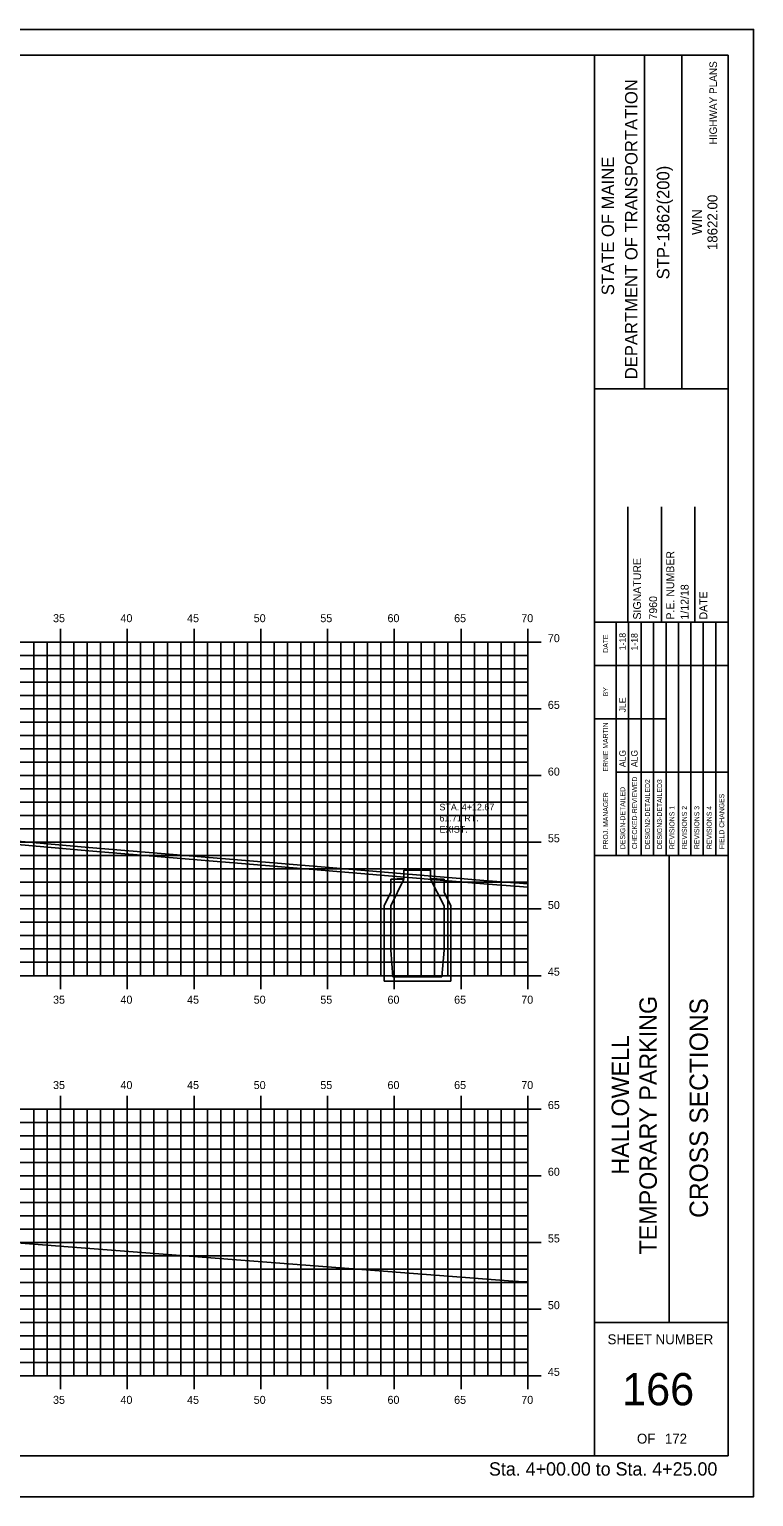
# Model space of a CAD drawing. Extents: x 1026213 to 1026383, y 394615 to 394725.
# Drawn here: x 1026329.1 to 1026383.3, y 394614.9 to 394724.9 of the extents above; entities that cross this region are included whole.
import ezdxf

# ---------------------------------------------------------------- set-up
doc = ezdxf.new("R2010")
doc.units = 0
for name, color, linetype in [('BORDER', 7, 'Continuous'), ('D_Text_Monospaced', 7, 'Continuous'), ('H_V ANNOTATION', 7, 'Continuous'), ('HIGHWAY_TITLE', 7, 'Continuous'), ('MAJOR', 7, 'Continuous'), ('MINOR', 7, 'Continuous'), ('PLOT BOUNDARY', 7, 'Continuous'), ('S_Roadway_Centerline', 7, 'Continuous'), ('S_Utilities_UG_Sanitary_MH', 7, 'Continuous')]:
    doc.layers.add(name, color=color, linetype=linetype)

msp = doc.modelspace()

# ---------------------------------------------------------------- linework, layer by layer
at = {"layer": 'BORDER'}
for p, q in [((1026381.43, 394722.93), (1026221.43, 394722.93)), ((1026371.43, 394617.93), (1026371.43, 394722.94)), ((1026375.16, 394697.93), (1026375.16, 394722.93)), ((1026377.96, 394697.93), (1026377.96, 394722.93)), ((1026381.43, 394617.93), (1026381.43, 394722.93)), ((1026371.43, 394697.93), (1026381.43, 394697.93)), ((1026373.93, 394680.44), (1026373.93, 394689.08)), ((1026376.43, 394680.44), (1026376.43, 394689.08)), ((1026378.93, 394680.44), (1026378.93, 394689.08)), ((1026371.43, 394680.44), (1026381.43, 394680.44)), ((1026371.43, 394662.94), (1026381.43, 394662.94)), ((1026377.02, 394627.94), (1026377.02, 394662.94)), ((1026371.43, 394627.94), (1026381.43, 394627.94)), ((1026221.43, 394617.93), (1026381.43, 394617.93))]:
    msp.add_line(p, q, dxfattribs=at)
for points in [[(1026373.05, 394677.19), (1026373.05, 394680.44)], [(1026373.98, 394662.94), (1026373.98, 394680.44)], [(1026374.91, 394680.44), (1026374.91, 394662.94)], [(1026375.84, 394662.94), (1026375.84, 394680.44)], [(1026376.78, 394662.94), (1026376.78, 394680.44)], [(1026377.71, 394662.94), (1026377.71, 394680.44)], [(1026378.64, 394662.94), (1026378.64, 394680.44)], [(1026379.57, 394662.94), (1026379.57, 394680.44)], [(1026380.5, 394662.94), (1026380.5, 394680.44)], [(1026373.05, 394662.94), (1026373.05, 394679.73)], [(1026371.43, 394677.19), (1026381.43, 394677.19)], [(1026371.43, 394673.19), (1026373.05, 394673.19)], [(1026373.05, 394673.19), (1026376.78, 394673.19)], [(1026373.05, 394669.19), (1026381.43, 394669.19)]]:
    msp.add_lwpolyline(points, dxfattribs=at)
at = {"layer": 'MAJOR'}
for p, q in [((1026226.43, 394678.93), (1026366.43, 394678.93)), ((1026331.43, 394679.93), (1026331.43, 394678.93)), ((1026331.43, 394653.93), (1026331.43, 394678.93)), ((1026336.43, 394679.93), (1026336.43, 394678.93)), ((1026336.43, 394653.93), (1026336.43, 394678.93)), ((1026341.43, 394679.93), (1026341.43, 394678.93)), ((1026341.43, 394653.93), (1026341.43, 394678.93)), ((1026346.43, 394679.93), (1026346.43, 394678.93)), ((1026346.43, 394653.93), (1026346.43, 394678.93)), ((1026351.43, 394679.93), (1026351.43, 394678.93)), ((1026351.43, 394653.93), (1026351.43, 394678.93)), ((1026356.43, 394679.93), (1026356.43, 394678.93)), ((1026356.43, 394653.93), (1026356.43, 394678.93)), ((1026361.43, 394679.93), (1026361.43, 394678.93)), ((1026361.43, 394653.93), (1026361.43, 394678.93)), ((1026367.44, 394678.93), (1026365.43, 394678.93)), ((1026366.43, 394679.93), (1026366.43, 394678.93)), ((1026366.43, 394653.93), (1026366.43, 394678.93)), ((1026226.43, 394673.93), (1026366.43, 394673.93)), ((1026367.44, 394673.93), (1026365.43, 394673.93)), ((1026226.43, 394668.93), (1026366.43, 394668.93)), ((1026367.44, 394668.93), (1026365.43, 394668.93)), ((1026226.43, 394663.93), (1026366.43, 394663.93)), ((1026367.44, 394663.93), (1026365.43, 394663.93)), ((1026226.43, 394658.93), (1026366.43, 394658.93)), ((1026367.44, 394658.93), (1026365.43, 394658.93)), ((1026226.43, 394653.93), (1026366.43, 394653.93)), ((1026331.43, 394652.93), (1026331.43, 394653.93)), ((1026336.43, 394652.93), (1026336.43, 394653.93)), ((1026341.43, 394652.93), (1026341.43, 394653.93)), ((1026346.43, 394652.93), (1026346.43, 394653.93)), ((1026351.43, 394652.93), (1026351.43, 394653.93)), ((1026356.43, 394652.93), (1026356.43, 394653.93)), ((1026361.43, 394652.93), (1026361.43, 394653.93)), ((1026367.44, 394653.93), (1026365.43, 394653.93)), ((1026366.43, 394652.93), (1026366.43, 394653.93)), ((1026331.43, 394644.93), (1026331.43, 394643.93)), ((1026336.43, 394644.93), (1026336.43, 394643.93)), ((1026341.43, 394644.93), (1026341.43, 394643.93)), ((1026346.43, 394644.93), (1026346.43, 394643.93)), ((1026351.43, 394644.93), (1026351.43, 394643.93)), ((1026356.43, 394644.93), (1026356.43, 394643.93)), ((1026361.43, 394644.93), (1026361.43, 394643.93)), ((1026366.43, 394644.93), (1026366.43, 394643.93)), ((1026226.43, 394643.93), (1026366.43, 394643.93)), ((1026331.43, 394623.93), (1026331.43, 394643.93)), ((1026336.43, 394623.93), (1026336.43, 394643.93)), ((1026341.43, 394623.93), (1026341.43, 394643.93)), ((1026346.43, 394623.93), (1026346.43, 394643.93)), ((1026351.43, 394623.93), (1026351.43, 394643.93)), ((1026356.43, 394623.93), (1026356.43, 394643.93)), ((1026361.43, 394623.93), (1026361.43, 394643.93)), ((1026367.44, 394643.93), (1026365.43, 394643.93)), ((1026366.43, 394623.93), (1026366.43, 394643.93)), ((1026226.43, 394638.93), (1026366.43, 394638.93)), ((1026367.44, 394638.93), (1026365.43, 394638.93)), ((1026226.43, 394633.93), (1026366.43, 394633.93)), ((1026367.44, 394633.93), (1026365.43, 394633.93)), ((1026226.43, 394628.93), (1026366.43, 394628.93)), ((1026367.44, 394628.93), (1026365.43, 394628.93)), ((1026226.43, 394623.93), (1026366.43, 394623.93)), ((1026331.43, 394622.93), (1026331.43, 394623.93)), ((1026336.43, 394622.93), (1026336.43, 394623.93)), ((1026341.43, 394622.93), (1026341.43, 394623.93)), ((1026346.43, 394622.93), (1026346.43, 394623.93)), ((1026351.43, 394622.93), (1026351.43, 394623.93)), ((1026356.43, 394622.93), (1026356.43, 394623.93)), ((1026361.43, 394622.93), (1026361.43, 394623.93)), ((1026367.44, 394623.93), (1026365.43, 394623.93)), ((1026366.43, 394622.93), (1026366.43, 394623.93))]:
    msp.add_line(p, q, dxfattribs=at)
at = {"layer": 'MINOR'}
for p, q in [((1026329.43, 394653.93), (1026329.43, 394678.93)), ((1026330.43, 394653.93), (1026330.43, 394678.93)), ((1026332.43, 394653.93), (1026332.43, 394678.93)), ((1026333.43, 394653.93), (1026333.43, 394678.93)), ((1026334.43, 394653.93), (1026334.43, 394678.93)), ((1026335.43, 394653.93), (1026335.43, 394678.93)), ((1026337.43, 394653.93), (1026337.43, 394678.93)), ((1026338.43, 394653.93), (1026338.43, 394678.93)), ((1026339.43, 394653.93), (1026339.43, 394678.93)), ((1026340.43, 394653.93), (1026340.43, 394678.93)), ((1026342.43, 394653.93), (1026342.43, 394678.93)), ((1026343.43, 394653.93), (1026343.43, 394678.93)), ((1026344.43, 394653.93), (1026344.43, 394678.93)), ((1026345.43, 394653.93), (1026345.43, 394678.93)), ((1026347.43, 394653.93), (1026347.43, 394678.93)), ((1026348.43, 394653.93), (1026348.43, 394678.93)), ((1026349.43, 394653.93), (1026349.43, 394678.93)), ((1026350.43, 394653.93), (1026350.43, 394678.93)), ((1026352.43, 394653.93), (1026352.43, 394678.93)), ((1026353.43, 394653.93), (1026353.43, 394678.93)), ((1026354.43, 394653.93), (1026354.43, 394678.93)), ((1026355.43, 394653.93), (1026355.43, 394678.93)), ((1026357.43, 394653.93), (1026357.43, 394678.93)), ((1026358.43, 394653.93), (1026358.43, 394678.93)), ((1026359.43, 394653.93), (1026359.43, 394678.93)), ((1026360.43, 394653.93), (1026360.43, 394678.93)), ((1026362.43, 394653.93), (1026362.43, 394678.93)), ((1026363.43, 394653.93), (1026363.43, 394678.93)), ((1026364.43, 394653.93), (1026364.43, 394678.93)), ((1026365.43, 394653.93), (1026365.43, 394678.93)), ((1026226.43, 394677.93), (1026366.43, 394677.93)), ((1026366.43, 394677.93), (1026365.43, 394677.93)), ((1026226.43, 394676.93), (1026366.43, 394676.93)), ((1026366.43, 394676.93), (1026365.43, 394676.93)), ((1026226.43, 394675.93), (1026366.43, 394675.93)), ((1026366.43, 394675.93), (1026365.43, 394675.93)), ((1026226.43, 394674.93), (1026366.43, 394674.93)), ((1026366.43, 394674.93), (1026365.43, 394674.93)), ((1026226.43, 394672.93), (1026366.43, 394672.93)), ((1026366.43, 394672.93), (1026365.43, 394672.93)), ((1026226.43, 394671.93), (1026366.43, 394671.93)), ((1026366.43, 394671.93), (1026365.43, 394671.93)), ((1026226.43, 394670.93), (1026366.43, 394670.93)), ((1026366.43, 394670.93), (1026365.43, 394670.93)), ((1026226.43, 394669.93), (1026366.43, 394669.93)), ((1026366.43, 394669.93), (1026365.43, 394669.93)), ((1026226.43, 394667.93), (1026366.43, 394667.93)), ((1026366.43, 394667.93), (1026365.43, 394667.93)), ((1026226.43, 394666.93), (1026366.43, 394666.93)), ((1026366.43, 394666.93), (1026365.43, 394666.93)), ((1026226.43, 394665.93), (1026366.43, 394665.93)), ((1026366.43, 394665.93), (1026365.43, 394665.93)), ((1026226.43, 394664.93), (1026366.43, 394664.93)), ((1026366.43, 394664.93), (1026365.43, 394664.93)), ((1026226.43, 394662.93), (1026366.43, 394662.93)), ((1026366.43, 394662.93), (1026365.43, 394662.93)), ((1026226.43, 394661.93), (1026366.43, 394661.93)), ((1026366.43, 394661.93), (1026365.43, 394661.93)), ((1026226.43, 394660.93), (1026366.43, 394660.93)), ((1026366.43, 394660.93), (1026365.43, 394660.93)), ((1026226.43, 394659.93), (1026366.43, 394659.93)), ((1026366.43, 394659.93), (1026365.43, 394659.93)), ((1026226.43, 394657.93), (1026366.43, 394657.93)), ((1026226.43, 394656.93), (1026366.43, 394656.93)), ((1026366.43, 394657.93), (1026365.43, 394657.93)), ((1026366.43, 394656.93), (1026365.43, 394656.93)), ((1026226.43, 394655.93), (1026366.43, 394655.93)), ((1026366.43, 394655.93), (1026365.43, 394655.93)), ((1026226.43, 394654.93), (1026366.43, 394654.93)), ((1026366.43, 394654.93), (1026365.43, 394654.93)), ((1026329.43, 394623.93), (1026329.43, 394643.93)), ((1026330.43, 394623.93), (1026330.43, 394643.93)), ((1026332.43, 394623.93), (1026332.43, 394643.93)), ((1026333.43, 394623.93), (1026333.43, 394643.93)), ((1026334.43, 394623.93), (1026334.43, 394643.93)), ((1026335.43, 394623.93), (1026335.43, 394643.93)), ((1026337.43, 394623.93), (1026337.43, 394643.93)), ((1026338.43, 394623.93), (1026338.43, 394643.93)), ((1026339.43, 394623.93), (1026339.43, 394643.93)), ((1026340.43, 394623.93), (1026340.43, 394643.93)), ((1026342.43, 394623.93), (1026342.43, 394643.93)), ((1026343.43, 394623.93), (1026343.43, 394643.93)), ((1026344.43, 394623.93), (1026344.43, 394643.93)), ((1026345.43, 394623.93), (1026345.43, 394643.93)), ((1026347.43, 394623.93), (1026347.43, 394643.93)), ((1026348.43, 394623.93), (1026348.43, 394643.93)), ((1026349.43, 394623.93), (1026349.43, 394643.93)), ((1026350.43, 394623.93), (1026350.43, 394643.93)), ((1026352.43, 394623.93), (1026352.43, 394643.93)), ((1026353.43, 394623.93), (1026353.43, 394643.93)), ((1026354.43, 394623.93), (1026354.43, 394643.93)), ((1026355.43, 394623.93), (1026355.43, 394643.93)), ((1026357.43, 394623.93), (1026357.43, 394643.93)), ((1026358.43, 394623.93), (1026358.43, 394643.93)), ((1026359.43, 394623.93), (1026359.43, 394643.93)), ((1026360.43, 394623.93), (1026360.43, 394643.93)), ((1026362.43, 394623.93), (1026362.43, 394643.93)), ((1026363.43, 394623.93), (1026363.43, 394643.93)), ((1026364.43, 394623.93), (1026364.43, 394643.93)), ((1026365.43, 394623.93), (1026365.43, 394643.93)), ((1026226.43, 394642.93), (1026366.43, 394642.93)), ((1026366.43, 394642.93), (1026365.43, 394642.93)), ((1026226.43, 394641.93), (1026366.43, 394641.93)), ((1026366.43, 394641.93), (1026365.43, 394641.93)), ((1026226.43, 394640.93), (1026366.43, 394640.93)), ((1026366.43, 394640.93), (1026365.43, 394640.93)), ((1026226.43, 394639.93), (1026366.43, 394639.93)), ((1026366.43, 394639.93), (1026365.43, 394639.93)), ((1026226.43, 394637.93), (1026366.43, 394637.93)), ((1026366.43, 394637.93), (1026365.43, 394637.93)), ((1026226.43, 394636.93), (1026366.43, 394636.93)), ((1026366.43, 394636.93), (1026365.43, 394636.93)), ((1026226.43, 394635.93), (1026366.43, 394635.93)), ((1026226.43, 394634.93), (1026366.43, 394634.93)), ((1026366.43, 394635.93), (1026365.43, 394635.93)), ((1026366.43, 394634.93), (1026365.43, 394634.93)), ((1026226.43, 394632.93), (1026366.43, 394632.93)), ((1026366.43, 394632.93), (1026365.43, 394632.93)), ((1026226.43, 394631.93), (1026366.43, 394631.93)), ((1026366.43, 394631.93), (1026365.43, 394631.93)), ((1026226.43, 394630.93), (1026366.43, 394630.93)), ((1026366.43, 394630.93), (1026365.43, 394630.93)), ((1026226.43, 394629.93), (1026366.43, 394629.93)), ((1026366.43, 394629.93), (1026365.43, 394629.93)), ((1026226.43, 394627.93), (1026366.43, 394627.93)), ((1026366.43, 394627.93), (1026365.43, 394627.93)), ((1026226.43, 394626.93), (1026366.43, 394626.93)), ((1026366.43, 394626.93), (1026365.43, 394626.93)), ((1026226.43, 394625.93), (1026366.43, 394625.93)), ((1026366.43, 394625.93), (1026365.43, 394625.93)), ((1026226.43, 394624.93), (1026366.43, 394624.93)), ((1026366.43, 394624.93), (1026365.43, 394624.93))]:
    msp.add_line(p, q, dxfattribs=at)
at = {"layer": 'PLOT BOUNDARY'}
msp.add_lwpolyline([(1026213.34, 394614.87), (1026383.34, 394614.87), (1026383.34, 394724.87), (1026213.34, 394724.87)], close=True, dxfattribs=at)
at = {"layer": 'S_Roadway_Centerline'}
for points in [[(1026256.36, 394669.08), (1026256.36, 394669.08), (1026258.36, 394668.94), (1026278.77, 394667.41), (1026280.04, 394667.3), (1026280.16, 394667.29), (1026299.85, 394666.05), (1026302.39, 394665.94), (1026303.98, 394665.86), (1026303.98, 394665.86), (1026303.98, 394665.86), (1026309.14, 394665.64), (1026309.14, 394665.64), (1026312.05, 394665.32), (1026323.69, 394664.41), (1026333.54, 394663.54), (1026333.54, 394663.54), (1026333.55, 394663.54), (1026346.49, 394662.46), (1026346.49, 394662.46), (1026363.44, 394661.04), (1026365.47, 394660.9), (1026365.47, 394660.9), (1026366.43, 394660.82)], [(1026256.36, 394668.83), (1026256.36, 394668.83), (1026258.36, 394668.69), (1026278.77, 394667.16), (1026280.04, 394667.05), (1026280.16, 394667.04), (1026299.85, 394665.8), (1026302.39, 394665.69), (1026303.98, 394665.61), (1026303.98, 394665.61), (1026303.98, 394665.61), (1026309.14, 394665.39), (1026309.14, 394665.39), (1026312.05, 394665.07), (1026323.69, 394664.16), (1026333.54, 394663.29), (1026333.54, 394663.29), (1026333.55, 394663.29), (1026346.49, 394662.21), (1026346.49, 394662.21), (1026363.44, 394660.79), (1026365.47, 394660.65), (1026365.47, 394660.65), (1026366.43, 394660.57)], [(1026328.45, 394633.87), (1026365.64, 394631.01), (1026365.64, 394631.01), (1026365.73, 394631.01), (1026366.43, 394630.97)]]:
    msp.add_lwpolyline(points, dxfattribs=at)
at = {"layer": 'S_Utilities_UG_Sanitary_MH'}
for p, q in [((1026356.16, 394661.16), (1026357.15, 394661.16)), ((1026357.15, 394661.16), (1026356.16, 394659.16)), ((1026356.16, 394660.18), (1026356.16, 394661.16)), ((1026356.16, 394661.16), (1026357.15, 394661.16)), ((1026357.15, 394661.16), (1026356.16, 394659.16)), ((1026356.16, 394660.18), (1026356.16, 394661.16)), ((1026360.16, 394659.16), (1026359.15, 394661.16)), ((1026359.15, 394661.16), (1026360.16, 394661.16)), ((1026360.16, 394659.16), (1026359.15, 394661.16)), ((1026359.15, 394661.16), (1026360.16, 394661.16)), ((1026360.16, 394661.16), (1026360.16, 394660.18)), ((1026360.16, 394661.16), (1026360.16, 394660.18)), ((1026355.67, 394659.16), (1026356.16, 394660.18)), ((1026355.67, 394659.16), (1026356.16, 394660.18)), ((1026355.67, 394653.52), (1026355.67, 394659.16)), ((1026355.67, 394653.52), (1026355.67, 394659.16)), ((1026356.16, 394659.16), (1026356.16, 394655.85)), ((1026356.16, 394659.16), (1026356.16, 394655.85)), ((1026360.16, 394660.18), (1026360.66, 394659.16)), ((1026360.16, 394660.18), (1026360.66, 394659.16)), ((1026360.16, 394655.85), (1026360.16, 394659.16)), ((1026360.16, 394655.85), (1026360.16, 394659.16)), ((1026360.66, 394659.16), (1026360.66, 394653.52)), ((1026360.66, 394659.16), (1026360.66, 394653.52)), ((1026356.16, 394655.85), (1026356.33, 394653.84)), ((1026356.16, 394655.85), (1026356.33, 394653.84)), ((1026360, 394653.84), (1026360.16, 394655.85)), ((1026360, 394653.84), (1026360.16, 394655.85)), ((1026356.33, 394653.84), (1026360, 394653.84)), ((1026356.33, 394653.84), (1026360, 394653.84)), ((1026360.66, 394653.52), (1026355.67, 394653.52)), ((1026360.66, 394653.52), (1026355.67, 394653.52))]:
    msp.add_line(p, q, dxfattribs=at)
msp.add_lwpolyline([(1026359.64, 394661.2), (1026359.15, 394661.2), (1026359.15, 394661.83), (1026357.15, 394661.83), (1026357.15, 394661.2), (1026356.65, 394661.2)], dxfattribs=at)
msp.add_lwpolyline([(1026359.64, 394661.2), (1026359.15, 394661.2), (1026359.15, 394661.83), (1026357.15, 394661.83), (1026357.15, 394661.2), (1026356.65, 394661.2)], dxfattribs=at)

# ---------------------------------------------------------------- texts
at = {"layer": 'BORDER'}
for s, height, rotation, p in [('DEPARTMENT OF TRANSPORTATION', 0.9318, 90, (1026374.64, 394698.64)), ('STATE OF MAINE', 0.9318, 90, (1026372.89, 394704.94)), ('STP-1862(200)', 0.9318, 90, (1026377.03, 394706.13)), ('18622.00', 0.745, 90, (1026380.63, 394708.32)), ('WIN', 0.745, 90, (1026379.47, 394709.46)), ('P.E. NUMBER', 0.5906, 90, (1026377.39, 394680.63)), ('SIGNATURE', 0.591, 90, (1026374.91, 394680.63)), ('7960', 0.591, 90, (1026376.11, 394680.63)), ('1/12/18', 0.591, 90, (1026378.47, 394680.63)), ('DATE', 0.591, 90, (1026379.87, 394680.63)), ('DATE', 0.371, 90, (1026372.44, 394678.14)), ('1-18', 0.485, 90, (1026373.76, 394678.33)), ('1-18', 0.485, 90, (1026374.65, 394678.31)), ('BY', 0.371, 90, (1026372.44, 394674.87)), ('JLE', 0.485, 90, (1026373.76, 394673.67)), ('ERNIE MARTIN', 0.3727, 90, (1026372.44, 394669.23)), ('ALG', 0.485, 90, (1026373.76, 394669.56)), ('ALG', 0.485, 90, (1026374.65, 394669.56)), ('DESIGN-DETAILED', 0.3727, 90, (1026373.72, 394663.42)), ('CHECKED-REVIEWED', 0.3727, 90, (1026374.61, 394663.42)), ('DESIGN2-DETAILED2', 0.3727, 90, (1026375.58, 394663.42)), ('DESIGN3-DETAILED3', 0.3727, 90, (1026376.48, 394663.42)), ('PROJ. MANAGER', 0.3727, 90, (1026372.44, 394663.42)), ('FIELD CHANGES', 0.3727, 90, (1026381.14, 394663.42)), ('REVISIONS 1', 0.3727, 90, (1026377.41, 394663.42)), ('REVISIONS 2', 0.3727, 90, (1026378.34, 394663.42)), ('REVISIONS 3', 0.3727, 90, (1026379.27, 394663.42)), ('REVISIONS 4', 0.3727, 90, (1026380.2, 394663.42)), ('CROSS SECTIONS', 1.3779, 90, (1026379.92, 394635.77)), ('SHEET NUMBER', 0.7453, 360, (1026372.4, 394626.3)), ('166', 2.419, 360, (1026373.49, 394621.72)), ('OF', 0.745, 360, (1026374.6, 394618.85)), ('172', 0.745, 360, (1026376.69, 394618.85))]:
    msp.add_text(s, height=height, rotation=rotation, dxfattribs=at).set_placement(p)
at = {"layer": 'D_Text_Monospaced'}
for s, p in [('STA. 4+12.67', (1026359.81, 394666.32)), ('STA. 4+12.67', (1026359.81, 394666.32)), ('61.71 RT.', (1026359.81, 394665.49)), ('61.71 RT.', (1026359.81, 394665.49)), ('EXIST. ', (1026359.81, 394664.65)), ('EXIST. ', (1026359.81, 394664.65))]:
    msp.add_text(s, height=0.5, dxfattribs=at).set_placement(p)
at = {"layer": 'H_V ANNOTATION'}
for s, height, p in [('35', 0.6, (1026330.87, 394680.43)), ('40', 0.6, (1026335.92, 394680.43)), ('45', 0.6, (1026340.91, 394680.43)), ('50', 0.6, (1026345.9, 394680.43)), ('55', 0.6, (1026350.89, 394680.43)), ('60', 0.6, (1026355.92, 394680.43)), ('65', 0.6, (1026360.91, 394680.43)), ('70', 0.6, (1026365.94, 394680.43)), ('70', 0.6, (1026367.93, 394678.93)), ('65', 0.6, (1026367.93, 394673.93)), ('60', 0.6, (1026367.93, 394668.93)), ('55', 0.6, (1026367.93, 394663.93)), ('50', 0.6, (1026367.93, 394658.93)), ('45', 0.6, (1026367.93, 394653.93)), ('35', 0.6, (1026330.87, 394651.83)), ('40', 0.6, (1026335.92, 394651.83)), ('45', 0.6, (1026340.91, 394651.83)), ('50', 0.6, (1026345.9, 394651.83)), ('55', 0.6, (1026350.89, 394651.83)), ('60', 0.6, (1026355.92, 394651.83)), ('65', 0.6, (1026360.91, 394651.83)), ('70', 0.6, (1026365.94, 394651.83)), ('35', 0.6, (1026330.87, 394645.43)), ('40', 0.6, (1026335.92, 394645.43)), ('45', 0.6, (1026340.91, 394645.43)), ('50', 0.6, (1026345.9, 394645.43)), ('55', 0.6, (1026350.89, 394645.43)), ('60', 0.6, (1026355.92, 394645.43)), ('65', 0.6, (1026360.91, 394645.43)), ('70', 0.6, (1026365.94, 394645.43)), ('65', 0.6, (1026367.93, 394643.93)), ('60', 0.6, (1026367.93, 394638.93)), ('55', 0.6, (1026367.93, 394633.93)), ('50', 0.6, (1026367.93, 394628.93)), ('45', 0.6, (1026367.93, 394623.93)), ('35', 0.6, (1026330.87, 394621.83)), ('40', 0.6, (1026335.92, 394621.83)), ('45', 0.6, (1026340.91, 394621.83)), ('50', 0.6, (1026345.9, 394621.83)), ('55', 0.6, (1026350.89, 394621.83)), ('60', 0.6, (1026355.92, 394621.83)), ('65', 0.6, (1026360.91, 394621.83)), ('70', 0.6, (1026365.94, 394621.83)), ('Sta. 4+00.00 to Sta. 4+25.00', 1.0002, (1026363.52, 394616.45))]:
    msp.add_text(s, height=height, dxfattribs=at).set_placement(p)
at = {"layer": 'HIGHWAY_TITLE'}
for s, height, p in [('HIGHWAY PLANS', 0.559, (1026380.59, 394716.25)), ('TEMPORARY PARKING', 1.3043, (1026376.09, 394633.03)), ('HALLOWELL', 1.304, (1026374.01, 394639.01))]:
    msp.add_text(s, height=height, rotation=90, dxfattribs=at).set_placement(p)

doc.saveas('drawing.dxf')
